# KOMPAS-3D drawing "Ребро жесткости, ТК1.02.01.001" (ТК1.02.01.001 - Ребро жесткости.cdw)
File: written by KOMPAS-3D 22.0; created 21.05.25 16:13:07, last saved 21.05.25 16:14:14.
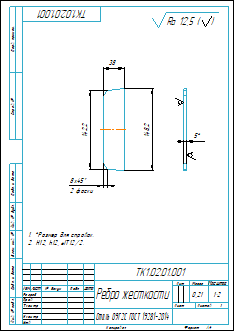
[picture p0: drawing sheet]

Sheet 1: A4, portrait

Document properties: Автор: TC; Знак неуказанной шероховатости: 4; Параметр неуказанной шероховатости: Ra 12,5; Масса: 0.212581

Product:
- Part/product: Ребро жесткости  | designation ТК1.02.01.001
    Материал: Сталь 09Г2С ГОСТ 19281-2014 (density 7850 kg/m3)
    Масса: 0.212581
    Форматы листов документа: A4

Title block, sheet 1: Наименование: Ребро жесткости; designation: ТК1.02.01.001; Материал: Сталь 09Г2С ГОСТ 19281-2014; Масса: 0,21; Количество листов документа: 1; Форматы листов документа: A4; stored path: D:\Рабочая папка\АРХИВ\612\05\Задание №6 - Тележка для крыши\3Д\Рама направляющих\ТК1.02.01.001 - Ребро жесткости.cdw

Views: Вид 1, Слева, Проекционный вид 2
Referenced files in D:\Рабочая папка\АРХИВ\612\05\Задание №6 - Тележка для крыши\3Д\Рама направляющих\: Ребро жесткости.m3d
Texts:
  Ra 12,5
  Ra 12,5 ( )
  BOSimple***Material:4ccf0190-16b6-4223-9222-aa108d28a442
  ТК1.02.01.001 Ребро жесткости
Dimensions and other numbers on the sheet: 148,2; 38; 142,2; 8; 2 фаски; 5; 1:2; 1; 0,21

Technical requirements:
  *Размер для справок.
  H12, h12, ±IT12/2.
